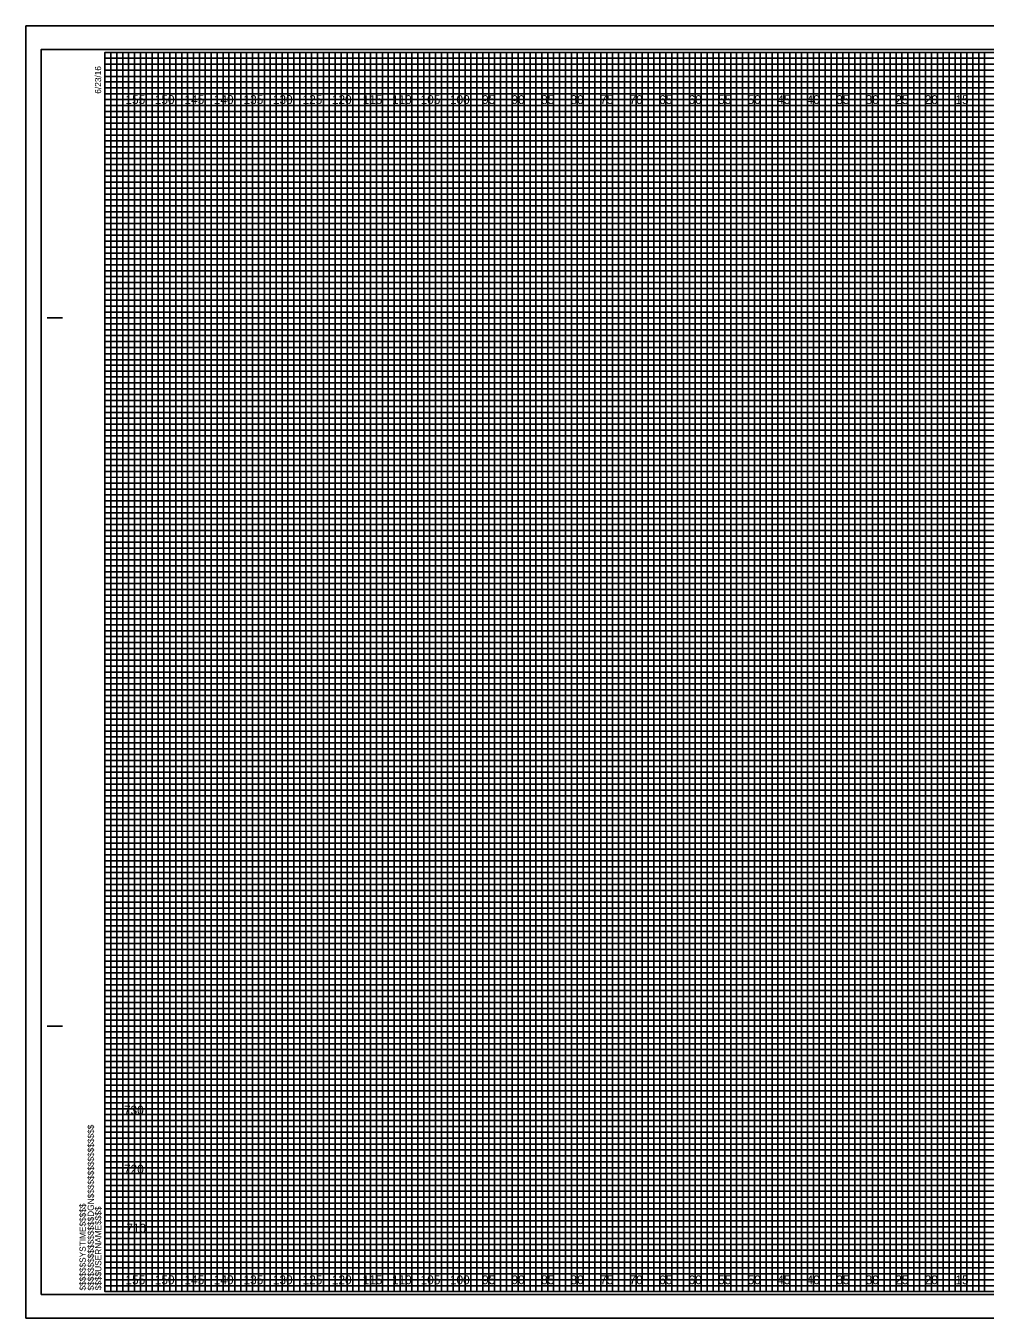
# Model space of a CAD drawing. Extents: x -13 to 323, y -5 to 654.
# Drawn here: x -13.4 to 149.1, y 435.5 to 654.5 of the extents above; entities that cross this region are included whole.
import ezdxf

# ---------------------------------------------------------------- set-up
doc = ezdxf.new("R2010")
doc.units = 0
for name, color, linetype in [('Exist Cross Section Cell', 7, 'Continuous'), ('Exist XS Center Line Elevation Label', 7, 'Continuous'), ('Exist XS Ground Line', 7, 'Continuous'), ('Prop CMT Pvmt Course 2', 7, 'Continuous'), ('Prop CMT Pvmt Course 3', 7, 'Continuous'), ('Prop CMT Pvmt Surface', 7, 'Continuous'), ('Prop CMT Pvmt Surface Shoulder', 7, 'Continuous'), ('Prop CMT Shld Paved Course 1', 7, 'Continuous'), ('Prop CMT Shld Paved Course 2', 7, 'Continuous'), ('Prop CMT Subgrade Earthwork', 7, 'Continuous'), ('Scratch_Level_1', 7, 'Continuous')]:
    doc.layers.add(name, color=color, linetype=linetype)

msp = doc.modelspace()

# ---------------------------------------------------------------- linework, layer by layer
at = {"layer": 'Exist XS Center Line Elevation Label'}
for points in [[(0, 650), (5, 650), (5, 440), (15, 440), (15, 650), (25, 650), (25, 440), (35, 440), (35, 650), (45, 650), (45, 440), (55, 440), (55, 650), (65, 650), (65, 440), (75, 440), (75, 650), (85, 650), (85, 440), (95, 440), (95, 650), (105, 650), (105, 440), (115, 440), (115, 650), (125, 650), (125, 440), (135, 440), (135, 650), (145, 650), (145, 440), (155, 440)], [(0, 645), (275, 645)], [(0, 625), (320, 625), (320, 635), (0, 635)], [(0, 605), (320, 605), (320, 615), (0, 615)], [(0, 585), (320, 585), (320, 595), (0, 595)], [(0, 565), (320, 565), (320, 575), (0, 575)], [(0, 545), (320, 545), (320, 555), (0, 555)], [(0, 525), (320, 525), (320, 535), (0, 535)], [(0, 505), (320, 505), (320, 515), (0, 515)], [(0, 485), (320, 485), (320, 495), (0, 495)], [(0, 465), (320, 465), (320, 475), (0, 475)], [(0, 445), (320, 445), (320, 455), (0, 455)]]:
    msp.add_lwpolyline(points, dxfattribs=at)
at = {"layer": 'Exist XS Ground Line'}
for p, q in [((10, 650), (0, 650)), ((10, 440), (10, 650)), ((30, 650), (20, 650)), ((20, 650), (20, 440)), ((30, 440), (30, 650)), ((50, 650), (40, 650)), ((40, 650), (40, 440)), ((50, 440), (50, 650)), ((70, 650), (60, 650)), ((60, 650), (60, 440)), ((70, 440), (70, 650)), ((90, 650), (80, 650)), ((80, 650), (80, 440)), ((90, 440), (90, 650)), ((110, 650), (100, 650)), ((100, 650), (100, 440)), ((110, 440), (110, 650)), ((130, 650), (120, 650)), ((120, 650), (120, 440)), ((130, 440), (130, 650)), ((150, 650), (140, 650)), ((140, 650), (140, 440)), ((20, 440), (10, 440)), ((40, 440), (30, 440)), ((60, 440), (50, 440)), ((80, 440), (70, 440)), ((100, 440), (90, 440)), ((120, 440), (110, 440)), ((140, 440), (130, 440))]:
    msp.add_line(p, q, dxfattribs=at)
for points in [[(0, 640), (320, 640), (320, 630), (0, 630)], [(0, 620), (320, 620), (320, 610), (0, 610)], [(0, 600), (320, 600), (320, 590), (0, 590)], [(0, 580), (320, 580), (320, 570), (0, 570)], [(0, 560), (320, 560), (320, 550), (0, 550)], [(0, 540), (320, 540), (320, 530), (0, 530)], [(0, 520), (320, 520), (320, 510), (0, 510)], [(0, 500), (320, 500), (320, 490), (0, 490)], [(0, 480), (320, 480), (320, 470), (0, 470)], [(0, 460), (320, 460), (320, 450), (0, 450)]]:
    msp.add_lwpolyline(points, dxfattribs=at)
at = {"layer": 'Prop CMT Pvmt Course 2'}
msp.add_lwpolyline([(-13.4, 435.5), (323.3, 435.5), (323.3, 654.5), (-13.4, 654.5)], close=True, dxfattribs=at)
at = {"layer": 'Prop CMT Pvmt Course 3'}
msp.add_lwpolyline([(-10.8, 439.5), (322.4, 439.5), (322.4, 650.5), (-10.8, 650.5)], close=True, dxfattribs=at)
msp.add_lwpolyline([(-10.8, 439.5), (322.4, 439.5), (322.4, 650.5), (-10.8, 650.5)], close=True, dxfattribs=at)
at = {"layer": 'Prop CMT Pvmt Surface'}
for p, q in [((323.3, 654.5), (-13.4, 654.5)), ((-13.4, 654.5), (-13.4, 435.5)), ((323.3, 654.5), (-13.4, 654.5)), ((-13.4, 654.5), (-13.4, 435.5)), ((-13.4, 435.5), (323.3, 435.5)), ((-13.4, 435.5), (323.3, 435.5))]:
    msp.add_line(p, q, dxfattribs=at)
at = {"layer": 'Prop CMT Shld Paved Course 1'}
for p, q in [((-9.8, 605), (-7.3, 605)), ((-9.7, 605), (-7.2, 605)), ((-9.8, 485), (-7.3, 485)), ((-9.7, 485), (-7.2, 485)), ((0, 440), (0, 440)), ((0, 440), (0, 440)), ((0, 440), (0, 440)), ((0, 440), (0, 440)), ((0, 440), (0, 440)), ((0, 440), (0, 440)), ((0, 440), (0, 440))]:
    msp.add_line(p, q, dxfattribs=at)
msp.add_lwpolyline([(320, 650), (0, 650), (0, 440), (320, 440)], close=True, dxfattribs=at)
at = {"layer": 'Prop CMT Shld Paved Course 2'}
for points in [[(0, 440), (1, 440), (1, 650), (2, 650), (2, 440)], [(2, 440), (3, 440), (3, 650), (4, 650), (4, 440)], [(5, 440), (6, 440), (6, 650), (7, 650), (7, 440)], [(7, 440), (8, 440), (8, 650), (9, 650), (9, 440)], [(10, 440), (11, 440), (11, 650), (12, 650), (12, 440)], [(12, 440), (13, 440), (13, 650), (14, 650), (14, 440)], [(15, 440), (16, 440), (16, 650), (17, 650), (17, 440)], [(17, 440), (18, 440), (18, 650), (19, 650), (19, 440)], [(20, 440), (21, 440), (21, 650), (22, 650), (22, 440)], [(22, 440), (23, 440), (23, 650), (24, 650), (24, 440)], [(25, 440), (26, 440), (26, 650), (27, 650), (27, 440)], [(27, 440), (28, 440), (28, 650), (29, 650), (29, 440)], [(30, 440), (31, 440), (31, 650), (32, 650), (32, 440)], [(32, 440), (33, 440), (33, 650), (34, 650), (34, 440)], [(35, 440), (36, 440), (36, 650), (37, 650), (37, 440)], [(37, 440), (38, 440), (38, 650), (39, 650), (39, 440)], [(40, 440), (41, 440), (41, 650), (42, 650), (42, 440)], [(42, 440), (43, 440), (43, 650), (44, 650), (44, 440)], [(45, 440), (46, 440), (46, 650), (47, 650), (47, 440)], [(47, 440), (48, 440), (48, 650), (49, 650), (49, 440)], [(50, 440), (51, 440), (51, 650), (52, 650), (52, 440)], [(52, 440), (53, 440), (53, 650), (54, 650), (54, 440)], [(55, 440), (56, 440), (56, 650), (57, 650), (57, 440)], [(57, 440), (58, 440), (58, 650), (59, 650), (59, 440)], [(60, 440), (61, 440), (61, 650), (62, 650), (62, 440)], [(62, 440), (63, 440), (63, 650), (64, 650), (64, 440)], [(65, 440), (66, 440), (66, 650), (67, 650), (67, 440)], [(67, 440), (68, 440), (68, 650), (69, 650), (69, 440)], [(70, 440), (71, 440), (71, 650), (72, 650), (72, 440)], [(72, 440), (73, 440), (73, 650), (74, 650), (74, 440)], [(75, 440), (76, 440), (76, 650), (77, 650), (77, 440)], [(77, 440), (78, 440), (78, 650), (79, 650), (79, 440)], [(80, 440), (81, 440), (81, 650), (82, 650), (82, 440)], [(82, 440), (83, 440), (83, 650), (84, 650), (84, 440)], [(85, 440), (86, 440), (86, 650), (87, 650), (87, 440)], [(87, 440), (88, 440), (88, 650), (89, 650), (89, 440)], [(90, 440), (91, 440), (91, 650), (92, 650), (92, 440)], [(92, 440), (93, 440), (93, 650), (94, 650), (94, 440)], [(95, 440), (96, 440), (96, 650), (97, 650), (97, 440)], [(97, 440), (98, 440), (98, 650), (99, 650), (99, 440)], [(100, 440), (101, 440), (101, 650), (102, 650), (102, 440)], [(102, 440), (103, 440), (103, 650), (104, 650), (104, 440)], [(105, 440), (106, 440), (106, 650), (107, 650), (107, 440)], [(107, 440), (108, 440), (108, 650), (109, 650), (109, 440)], [(110, 440), (111, 440), (111, 650), (112, 650), (112, 440)], [(112, 440), (113, 440), (113, 650), (114, 650), (114, 440)], [(115, 440), (116, 440), (116, 650), (117, 650), (117, 440)], [(117, 440), (118, 440), (118, 650), (119, 650), (119, 440)], [(120, 440), (121, 440), (121, 650), (122, 650), (122, 440)], [(122, 440), (123, 440), (123, 650), (124, 650), (124, 440)], [(125, 440), (126, 440), (126, 650), (127, 650), (127, 440)], [(127, 440), (128, 440), (128, 650), (129, 650), (129, 440)], [(130, 440), (131, 440), (131, 650), (132, 650), (132, 440)], [(132, 440), (133, 440), (133, 650), (134, 650), (134, 440)], [(135, 440), (136, 440), (136, 650), (137, 650), (137, 440)], [(137, 440), (138, 440), (138, 650), (139, 650), (139, 440)], [(140, 440), (141, 440), (141, 650), (142, 650), (142, 440)], [(142, 440), (143, 440), (143, 650), (144, 650), (144, 440)], [(145, 440), (146, 440), (146, 650), (147, 650), (147, 440)], [(147, 440), (148, 440), (148, 650), (149, 650), (149, 440)]]:
    msp.add_lwpolyline(points, dxfattribs=at)
at = {"layer": 'Prop CMT Subgrade Earthwork'}
for p, q in [((10, 440), (10, 650)), ((10, 440), (10, 650)), ((20, 440), (20, 650)), ((20, 440), (20, 650)), ((30, 440), (30, 650)), ((30, 440), (30, 650)), ((40, 440), (40, 650)), ((40, 440), (40, 650)), ((50, 440), (50, 650)), ((50, 440), (50, 650)), ((60, 440), (60, 650)), ((60, 440), (60, 650)), ((70, 440), (70, 650)), ((70, 440), (70, 650)), ((80, 440), (80, 650)), ((80, 440), (80, 650)), ((90, 440), (90, 650)), ((90, 440), (90, 650)), ((100, 440), (100, 650)), ((100, 440), (100, 650)), ((110, 440), (110, 650)), ((110, 440), (110, 650)), ((120, 440), (120, 650)), ((120, 440), (120, 650)), ((130, 440), (130, 650)), ((130, 440), (130, 650)), ((140, 440), (140, 650)), ((140, 440), (140, 650)), ((0, 640), (320, 640)), ((0, 640), (320, 640)), ((0, 630), (320, 630)), ((0, 630), (320, 630)), ((0, 620), (320, 620)), ((0, 620), (320, 620)), ((0, 610), (320, 610)), ((0, 610), (320, 610)), ((0, 600), (320, 600)), ((0, 600), (320, 600)), ((0, 590), (320, 590)), ((0, 590), (320, 590)), ((0, 580), (320, 580)), ((0, 580), (320, 580)), ((0, 570), (320, 570)), ((0, 570), (320, 570)), ((0, 560), (320, 560)), ((0, 560), (320, 560)), ((0, 550), (320, 550)), ((0, 550), (320, 550)), ((0, 540), (320, 540)), ((0, 540), (320, 540)), ((0, 530), (320, 530)), ((0, 530), (320, 530)), ((0, 520), (320, 520)), ((0, 520), (320, 520)), ((0, 510), (320, 510)), ((0, 510), (320, 510)), ((0, 500), (320, 500)), ((0, 500), (320, 500)), ((0, 490), (320, 490)), ((0, 490), (320, 490)), ((0, 480), (320, 480)), ((0, 480), (320, 480)), ((0, 470), (320, 470)), ((0, 470), (320, 470)), ((0, 460), (320, 460)), ((0, 460), (320, 460)), ((0, 450), (320, 450)), ((0, 450), (320, 450))]:
    msp.add_line(p, q, dxfattribs=at)
at = {"layer": 'Scratch_Level_1'}
for p, q in [((0, 649), (260, 649)), ((260, 647.98), (0, 647.98)), ((0, 647.98), (0, 647)), ((0, 647), (260, 647)), ((260, 645.89), (0, 645.89)), ((0, 645.89), (0, 644)), ((0, 644), (320, 644))]:
    msp.add_line(p, q, dxfattribs=at)
for points in [[(0, 643), (270, 643), (320, 643), (320, 642), (0, 642)], [(0, 641), (320, 641), (320, 639), (0, 639)], [(0, 638), (320, 638), (320, 637), (0, 636.98)], [(0, 636), (320, 636), (320, 634), (0, 634)], [(0, 633), (320, 633), (320, 632), (0, 632)], [(0, 631), (320, 631), (320, 629), (0, 629)], [(0, 628), (320, 628), (320, 627), (0, 627)], [(0, 626), (320, 626), (320, 624), (0, 624)], [(0, 623), (320, 623), (320, 622), (0, 622)], [(0, 621), (320, 621), (320, 619), (0, 619)], [(0, 618), (320, 618), (320, 617), (0, 617)], [(0, 616), (320, 616), (320, 613.95), (320, 613), (320, 612), (0, 612)], [(0, 614), (320, 614), (320, 613), (0, 613)], [(0, 611), (320, 611), (320, 609), (0, 609.03)], [(0, 609.03), (320, 609), (320, 608), (0, 608)], [(0, 607), (320, 607), (320, 606), (0, 606)], [(0, 604), (320, 604), (320, 603), (0, 603)], [(0, 602), (320, 602), (320, 601), (0, 601)], [(-0.07, 598.89), (320, 598.89), (320, 597.88), (-0.07, 597.88)], [(0, 597), (320, 597), (320, 596), (0, 596)], [(0, 594), (320, 594), (320, 593), (0, 593)], [(0, 592), (320, 592), (320, 591), (0, 591)], [(0, 589), (320, 589), (320, 588), (0, 588)], [(0, 587), (320, 587), (320, 586), (0, 586)], [(0, 584), (320, 584), (320, 583), (0, 583)], [(0, 582), (320, 582), (320, 581), (0, 581)], [(0, 579), (320, 579), (319.99, 577.98), (0, 578)], [(0, 577), (320, 577), (320, 576), (0, 576)], [(0, 574), (320, 574), (320, 573), (0, 573)], [(0, 572), (320, 572), (320, 571), (0, 571)], [(0, 569), (320, 569), (320, 568), (0, 568)], [(0, 567), (320, 567), (320, 566), (0, 566)], [(0, 564), (320, 564), (320, 563), (0, 563)], [(0, 562), (320, 562), (320, 561), (0, 561)], [(0, 559), (320, 559), (320, 558), (0, 558)], [(0, 556.99), (320.07, 556.91), (320, 556), (0, 556)], [(0, 554), (320, 554), (320, 553), (0, 553)], [(0, 552), (320, 552), (320, 551), (0, 551)], [(0, 549), (320, 549), (320, 548), (0, 548)], [(0, 547), (320, 547), (320, 546), (0, 546)], [(0, 544), (320, 544), (320, 543), (0, 543)], [(0, 542), (320, 542), (320, 541), (0, 541)], [(0, 539), (320, 539), (320, 538), (0, 538)], [(0, 537), (320, 537), (320, 536), (0, 536)], [(0, 534), (320, 534), (320, 533), (0, 533)], [(0, 532), (320, 532), (320, 531), (0, 531)], [(0, 529), (320, 529), (320, 528), (0, 528)], [(0, 527), (320, 527), (320, 526), (0, 526)], [(0, 524), (320, 524), (320, 523), (0, 523)], [(0, 522), (320, 522), (320, 521), (0, 521)], [(0, 519), (320, 519), (319.99, 517.98), (0, 518)], [(0, 517), (320, 517), (320, 516), (0, 516)], [(0, 514), (320, 514), (320, 513), (0, 513)], [(0, 512), (320, 512), (320, 511), (0, 511)], [(0, 509), (320, 509), (320, 508), (0, 508)], [(0, 507), (320, 507), (320, 506), (0, 506)], [(0, 504), (320, 504), (320, 503), (0, 503)], [(0, 502), (320, 502), (320, 501), (0, 501)], [(0, 499), (320, 499), (320, 498), (0, 498)], [(0, 496.99), (320.07, 496.91), (320, 496), (0, 496)], [(0, 494), (320, 494), (320, 493), (0, 493)], [(0, 492), (320, 492), (320, 491), (0, 491)], [(0, 489), (320, 489), (320, 488), (0, 488)], [(0, 487), (320, 487), (320, 486), (0, 486)], [(0, 484), (320, 484), (320, 483), (0, 483)], [(0, 482), (320, 482), (320, 481), (0, 481)], [(0, 479), (320, 479), (320, 478), (0, 478)], [(0, 477), (320, 477), (320, 476), (0, 476)], [(0, 474), (320, 474), (320, 473), (0, 473)], [(0, 472), (320, 472), (320, 471), (0, 471)], [(0, 469), (320, 469), (320, 468), (0, 468)], [(0, 467), (320, 467), (320, 466), (0, 466)], [(0, 464), (320, 464), (320, 463), (0, 463)], [(0, 462), (320, 462), (320, 461), (0, 461)], [(0, 459), (320, 459), (320, 458), (0, 458)], [(0, 457), (320, 457), (320, 456), (0, 456)], [(0, 454), (320, 454), (320, 453), (0, 453)], [(0, 452), (320, 452), (320, 451), (0, 451)], [(0, 449), (320, 449), (320, 448), (0, 448)], [(0, 447), (320, 447), (320, 446), (0, 446)], [(0, 444), (320, 444), (320, 443), (0, 443)], [(0, 442), (320, 442), (320, 441), (0, 441)]]:
    msp.add_lwpolyline(points, dxfattribs=at)

# ---------------------------------------------------------------- texts
at = {"layer": 'Exist Cross Section Cell'}
for s, p in [('155', (3.47, 641.25)), ('150', (8.44, 641.25)), ('145', (13.47, 641.25)), ('140', (18.44, 641.25)), ('135', (23.47, 641.25)), ('130', (28.44, 641.25)), ('125', (33.47, 641.25)), ('120', (38.44, 641.25)), ('115', (43.65, 641.25)), ('110', (48.62, 641.25)), ('105', (53.47, 641.25)), ('100', (58.44, 641.25)), ('95', (63.88, 641.25)), ('90', (68.86, 641.25)), ('85', (73.88, 641.25)), ('80', (78.86, 641.25)), ('75', (83.88, 641.25)), ('70', (88.86, 641.25)), ('65', (93.88, 641.25)), ('60', (98.86, 641.25)), ('55', (103.88, 641.25)), ('50', (108.86, 641.25)), ('45', (113.88, 641.25)), ('40', (118.86, 641.25)), ('35', (123.88, 641.25)), ('30', (128.86, 641.25)), ('25', (133.88, 641.25)), ('20', (138.86, 641.25)), ('15', (144.06, 641.25)), ('155', (3.47, 441.25)), ('150', (8.44, 441.25)), ('145', (13.47, 441.25)), ('140', (18.44, 441.25)), ('135', (23.47, 441.25)), ('130', (28.44, 441.25)), ('125', (33.47, 441.25)), ('120', (38.44, 441.25)), ('115', (43.65, 441.25)), ('110', (48.62, 441.25)), ('105', (53.47, 441.25)), ('100', (58.44, 441.25)), ('95', (63.88, 441.25)), ('90', (68.86, 441.25)), ('85', (73.88, 441.25)), ('80', (78.86, 441.25)), ('75', (83.88, 441.25)), ('70', (88.86, 441.25)), ('65', (93.88, 441.25)), ('60', (98.86, 441.25)), ('55', (103.88, 441.25)), ('50', (108.86, 441.25)), ('45', (113.88, 441.25)), ('40', (118.86, 441.25)), ('35', (123.88, 441.25)), ('30', (128.86, 441.25)), ('25', (133.88, 441.25)), ('20', (138.86, 441.25)), ('15', (144.06, 441.25))]:
    msp.add_text(s, height=1.5, dxfattribs=at).set_placement(p)
at = {"layer": 'Prop CMT Pvmt Surface Shoulder'}
for s, p in [('730', (3.22, 470)), ('720', (3.23, 460)), ('710', (3.61, 450))]:
    msp.add_text(s, height=1.5, dxfattribs=at).set_placement(p)
at = {"layer": 'Prop CMT Shld Paved Course 1'}
for s, p in [('6/23/16', (-0.65, 643)), ('$$$$$$$$$$$$$$$$DGN$$$$$$$$$$$$$$$$', (-1.88, 440.18)), ('$$$$$$SYSTIME$$$$$', (-3.26, 440.18)), ('$$$$USERNAME$$$$', (-0.62, 440.23))]:
    msp.add_text(s, height=1.05, rotation=90, dxfattribs=at).set_placement(p)

doc.saveas('drawing.dxf')
